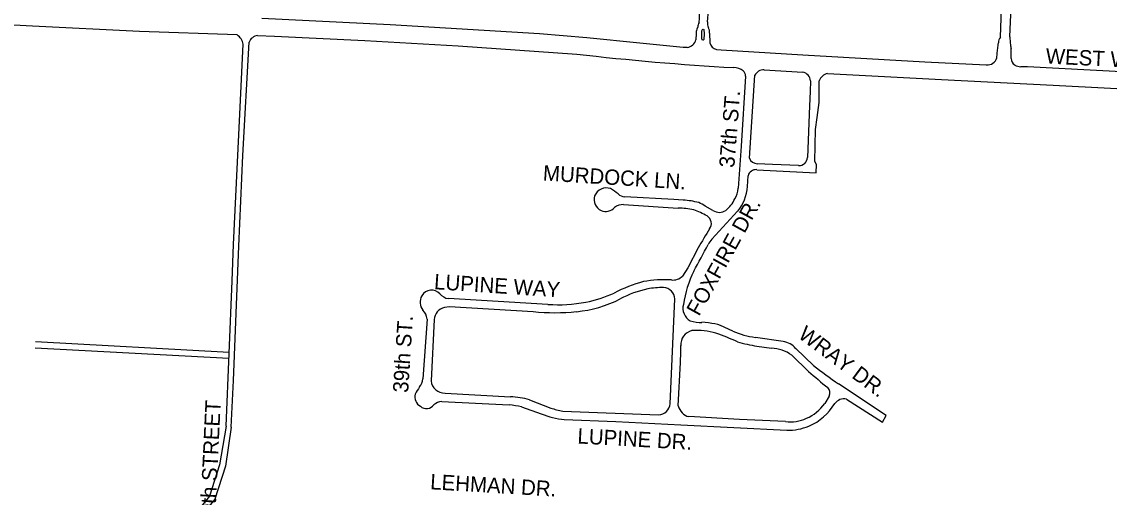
# Model space of a CAD drawing. Extents: x 0 to 712119, y 0 to 761125.
# Drawn here: x 670960 to 674515, y 734082 to 735635 of the extents above; entities that cross this region are included whole.
import ezdxf

# ---------------------------------------------------------------- set-up
doc = ezdxf.new("R2010")
doc.units = 0
doc.layers.add('PAVED ROADS', color=7, linetype='Continuous')
doc.layers.add('street names', color=7, linetype='Continuous')

msp = doc.modelspace()

# ---------------------------------------------------------------- linework, layer by layer
at = {"layer": 'PAVED ROADS'}
for points in [[(674190.6, 735585.7), (674202.1, 735851.2), (674211.1, 736038.3)], [(674159.6, 735584.9), (674172.2, 735923.2)], [(671664, 735592), (671344.7, 735603.9), (670995.3, 735620.5), (670627.9, 735640.5), (670515, 735647.1), (670407.6, 735652.5)], [(673204.3, 735672.2), (673201.4, 735635.2)], [(673135.9, 735551.5), (673122.4, 735551.5), (672980.2, 735565.2), (672807.6, 735583.1), (672653.2, 735595.3), (672164.1, 735625.6), (671744.8, 735645.8)], [(673169.9, 735618.3), (673166.6, 735610.5)], [(671730.4, 735590.2), (671786.5, 735588.6), (672081.4, 735574.2), (672387.1, 735556.7), (672774.3, 735529.6)], [(673164.8, 735596.4), (673163.7, 735576.5)], [(673208.3, 735597.7), (673209.3, 735566.3)], [(671628.2, 734313.8), (671648.2, 734788.9), (671652.6, 734907.7), (671672.7, 735333.1), (671683.5, 735562)], [(671645.1, 734310.8), (671652.5, 734463.6), (671670, 734902.6), (671682.6, 735198), (671703.2, 735568.8)], [(673231.9, 735544.7), (673246.1, 735543.6), (673513.5, 735527.2), (673912, 735504.4), (674113.3, 735495)], [(674152.3, 735560.4), (674152.9, 735566.7)], [(674195, 735515.5), (674194.7, 735547.6)], [(674147.7, 735517.7), (674150.2, 735543.4)], [(673387.4, 735477.8), (673513.5, 735470.5)], [(675324.4, 735431.5), (675158.7, 735439.1), (674678.4, 735465.1), (674248.3, 735487.6), (674226.5, 735488.3)], [(673326.5, 735457.6), (673312.2, 735228.9), (673301.8, 735091.6)], [(673338.8, 735189.5), (673356.3, 735460.8)], [(673363, 735152.1), (673557.5, 735141.5), (673558.5, 735169), (673553, 735179), (673555.5, 735283), (673560.5, 735322.5), (673566.5, 735371.5), (673566.5, 735405.5), (673567.5, 735442.5)], [(673538.8, 735442.5), (673537.2, 735407), (673535.2, 735361.1), (673529, 735191.5), (673529, 735191.5)], [(673594.5, 735466), (673966.8, 735446.2), (674332.5, 735427.8), (674707.4, 735408.2), (675022.3, 735391.3), (675316.1, 735376), (675619.4, 735358.2)], [(673500, 735165.6), (673415, 735169.5), (673364.5, 735171.5)], [(673332.6, 735096.7), (673334.6, 735132.4)], [(672909.5, 735072.8), (672909.5, 735072.8)], [(673122.5, 735052.7), (673091.6, 735055.1), (672931.4, 735063.8)], [(672926.9, 735038.5), (673105.9, 735026.8)], [(673219.7, 735019), (673194.8, 735033.4)], [(673216, 734925.5), (673300.5, 735016.6)], [(673171.3, 734897), (673137.8, 734831.4), (673119.8, 734804.7)], [(672680.3, 734712.2), (672354.9, 734730.9)], [(673079.8, 734387.5), (673095.2, 734729.9)], [(672632.1, 734688.3), (672358.8, 734703.6), (672342.6, 734702.1)], [(672285.1, 734664.3), (672271.2, 734468.5)], [(672307.9, 734662.2), (672298.2, 734462.2)], [(673205.7, 734651.4), (673183.9, 734653.5)], [(673284.8, 734624.8), (673244.9, 734643.2)], [(671004.8, 734590.5), (671638.4, 734556)], [(673449.1, 734591), (673358.7, 734604.1)], [(671003.7, 734570.6), (671637.3, 734536.1)], [(673363.5, 734575.8), (673410.9, 734569.1)], [(673548, 734512.7), (673490.8, 734567.5)], [(673106.3, 734380.5), (673113.2, 734522)], [(673477.3, 734545.8), (673532.5, 734493.4)], [(673656, 734402.5), (673774.4, 734327.6), (673786.6, 734349.2), (673630.6, 734452.1)], [(672343.9, 734422.2), (672557.4, 734409.8)], [(673600.2, 734412.5), (673585.1, 734388.4)], [(672333.1, 734394.4), (672553.7, 734383.7)], [(672593.8, 734377.8), (672658.5, 734355)], [(672620.4, 734399.9), (672689.3, 734373)], [(672728.6, 734363.8), (673041.5, 734350.9), (673041.5, 734350.9)], [(672733.8, 734336.4), (672902.7, 734329.6), (673114.8, 734318.2), (673461.7, 734300.9)], [(673456.9, 734329.2), (673306.9, 734335.8), (673141.2, 734345.4)], [(671628.2, 734313.8), (671606.3, 734188.3), (671573.3, 734086), (671479.7, 733970.8), (670892.3, 733656.6), (670780.5, 733554.9), (670717.5, 733481.9), (670667.6, 733372.4), (670635.4, 733024.1)], [(671645.1, 734310.8), (671625.7, 734183.5), (671591.2, 734076.3), (671492.6, 733955), (670903.9, 733640.1), (670794.8, 733540.9), (670734.5, 733471), (670687.2, 733367.2), (670655.3, 733022.2)]]:
    msp.add_lwpolyline(points, dxfattribs=at)
msp.add_lwpolyline([(673187.8, 735610.6), (673189.5, 735609.4), (673190.9, 735596), (673189.7, 735577.8), (673188, 735575.5), (673186, 735575.3), (673184.2, 735576.9), (673183.7, 735578.8), (673183.2, 735598.1), (673183.7, 735606), (673185.3, 735610.1)], close=True, dxfattribs=at)
for centre, radius, start, end in [((667863.6, 735945.8), 5320.2, 356.627, 358.805), ((673217.8, 735611.1), 48.4, 153.3774, 171.5393), ((673249.5, 735634.1), 48.1, 178.7737, 202.0103), ((673179.4, 735602), 29.1, 351.6265, 29.0808), ((671643.4, 735557.2), 40.4, 6.8411, 59.3655), ((671735, 735556.4), 34.1, 97.7387, 158.6796), ((673228.2, 735595.3), 63.4, 166.1269, 179.0535), ((674184.3, 735565.5), 31.4, 141.8981, 177.8311), ((674342.8, 735584.3), 152.2, 179.4886, 189.1822), ((673132.9, 735582.7), 31.4, 275.4441, 348.5494), ((673240, 735575.8), 32.2, 197.1368, 255.3489), ((674057, 735563.2), 95.3, 347.9767, 358.2642), ((674678.2, 735637.5), 491.8, 189.0624, 190.5365), ((673792.9, 744340.6), 8869.7, 263.4061, 266.73397), ((674118.6, 735524.3), 29.8, 259.8117, 347.1624), ((674217.4, 735513.8), 22.4, 175.5628, 242.0433), ((673287.1, 735434), 51.4, 52.2129, 89.4743), ((673305.4, 735458.1), 21.1, 358.6233, 51.4349), ((673399.4, 735430.9), 52.5, 125.6913, 145.1719), ((673383.3, 735452.8), 25.3, 80.6267, 125.1838), ((674226.5, 735525.1), 36.8, 237.8694, 270.0998), ((673506.8, 735438.9), 32.3, 6.2892, 77.9354), ((673601, 735431.2), 35.4, 100.6587, 161.412), ((673365.2, 735199.9), 28.4, 201.5415, 268.5264), ((673501.2, 735193.4), 27.8, 267.4364, 356.044), ((673360.8, 735124.9), 27.3, 85.4036, 163.8864), ((672872.2, 735049.5), 43, 72.4919, 157.237), ((672771.5, 734909.2), 214, 49.8543, 57.9165), ((673233.7, 735093.5), 68.1, 327.0329, 358.3898), ((673192.9, 735106.2), 140.1, 320.2288, 356.1092), ((672873.6, 735056), 42.3, 166.1725, 242.1399), ((672934.2, 735101.7), 38, 229.4647, 265.842), ((673106.4, 734793.6), 259.6, 75.0932, 86.4482), ((673202, 735095.6), 97.1, 308.0687, 336.2022), ((672868.6, 735056), 40.2, 248.5526, 317.7316), ((672930.1, 734981), 57.6, 93.169, 123.4634), ((673103.5, 734775.5), 251.2, 77.7046, 89.4444), ((673074.8, 734785.9), 249, 59.6638, 70.726), ((673095.7, 734867.2), 193.5, 59.1999, 66.39), ((673240.7, 735050.3), 37.6, 236.1068, 304.2618), ((673186.8, 734976.9), 27.6, 9.86, 60.2162), ((673186.7, 734975.7), 28, 322.3319, 12.2954), ((676663.9, 732808.5), 4069.4, 148.1057, 149.1214), ((666818.7, 738255.6), 7209.7, 331.54352, 332.33188), ((673296.1, 734858.7), 104.3, 140.1899, 151.9422), ((673089.4, 734833.7), 42, 262.6878, 316.347), ((673477.8, 734659.3), 358.5, 153.3368, 171.5453), ((673106, 734355.8), 445.3, 104.7734, 118.0064), ((673077.7, 734425.4), 344.7, 101.9271, 117.8986), ((673062.2, 734399.6), 393.1, 86.8077, 100.2292), ((673054.2, 734495.9), 271, 89.1494, 100.1469), ((673056.5, 734728.2), 38.8, 2.554, 87.4765), ((672305.9, 734719.1), 43.4, 151.0629, 217.2082), ((672299.9, 734721.9), 36.8, 42.367, 150.307), ((672361.7, 734775.4), 45, 219.6804, 261.2965), ((672735.2, 735085.1), 398.7, 275.5919, 297.032), ((672721.3, 735141.3), 429.8, 281.0612, 294.1034), ((672236.3, 734658.4), 49.2, 6.8672, 44.4857), ((672351.8, 734659.1), 44, 102.0216, 175.8637), ((672714.3, 735186.3), 475.3, 265.9005, 280.8535), ((673168.6, 734699.9), 47.1, 165.0532, 240.9652), ((672702.6, 735436.8), 751.8, 264.6169, 275.4526), ((673178.3, 734753.9), 100.6, 251.1444, 273.1834), ((673161.6, 734580.9), 46.7, 103.3101, 184.4893), ((673167.4, 734411.8), 215.2, 73.1702, 94.4125), ((673178.3, 734423.7), 229.4, 73.1396, 83.1378), ((673402.8, 734903.4), 302.6, 247.0467, 261.6228), ((672912.3, 733709.3), 962.3, 66.2452, 70.7408), ((673426.8, 735007.3), 436.1, 253.0896, 261.6587), ((673439.7, 734525.6), 66, 39.353, 81.84), ((672002.4, 734586.7), 1112.7, 356.6689, 359.5137), ((673407.3, 734452.7), 116.5, 53.0982, 88.2418), ((674358.5, 735408.7), 1232.9, 227.9359, 231.7731), ((674945.2, 736329.7), 2292.1, 232.4411, 235.0013), ((672446.7, 734309.6), 228.6, 144.466, 151.3836), ((672230.8, 734469.8), 40.4, 317.6588, 358.2889), ((672342.8, 734467.1), 44.9, 186.3666, 271.3958), ((672282.5, 734411.1), 37.3, 167.492, 239.0125), ((672558.7, 734213.4), 196.4, 71.6845, 90.3716), ((673576.9, 734422.9), 25.5, 336.0029, 42.7429), ((672283, 734402.4), 30.5, 229.7591, 323.4997), ((672335.2, 734351.9), 42.5, 92.8367, 130.582), ((672511.3, 733959.1), 426.7, 78.8544, 84.2936), ((672840.7, 734929.6), 576.8, 254.7809, 258.7861), ((673039.4, 734391.5), 40.6, 273.0408, 354.3633), ((673151.5, 734390.6), 46.3, 192.6031, 257.2116), ((673476.6, 734462), 131.1, 291.7501, 325.8717), ((673462.6, 734480.9), 181, 293.12, 329.0574), ((673647.9, 734366.5), 36.9, 77.2606, 144.673), ((672754.9, 734584.3), 248.8, 247.2024, 265.1331), ((673473.2, 734445.5), 117.4, 262.0448, 296.2887), ((673465.2, 734479.5), 178.6, 268.9021, 292.531)]:
    msp.add_arc(centre, radius, start, end, dxfattribs=at)

# ---------------------------------------------------------------- texts
at = {"layer": 'street names'}
for s, rotation, p in [('WEST WALNUT STREET', 357.2069, (674306.8, 735498.9)), ('37th ST.', 85.5078, (673289.5, 735157.3)), ('MURDOCK LN.', 356.3673, (672662.8, 735117)), ('FOXFIRE DR.', 61.1854, (673174.2, 734671.2)), ('LUPINE WAY', 356.2757, (672306.9, 734761.8)), ('39th ST.', 86.3501, (672223.1, 734422.3)), ('WRAY DR.', 323.2878, (673495, 734605.5)), ('40th STREET', 87.2905, (671591.3, 733985.6)), ('LUPINE DR.', 356.7744, (672775.7, 734258)), ('LEHMAN DR.', 356.6463, (672294.4, 734108.3))]:
    msp.add_text(s, height=50, rotation=rotation, dxfattribs=at).set_placement(p)

doc.saveas('drawing.dxf')
